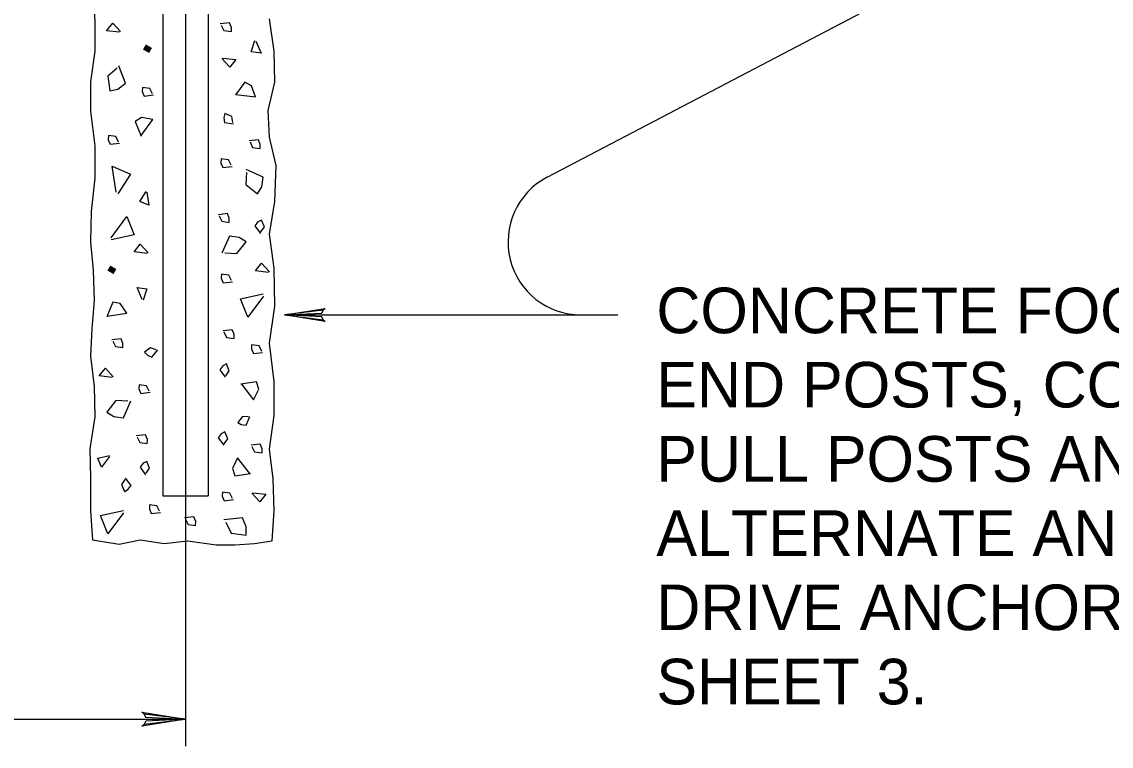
# Model space of a CAD drawing. Extents: x 13 to 918, y -903 to 879.
# Drawn here: x 538 to 612.7, y 510.4 to 560.1 of the extents above; entities that cross this region are included whole.
import ezdxf

# ---------------------------------------------------------------- set-up
doc = ezdxf.new("R2010")
doc.units = 0
doc.layers.add('2', color=7, linetype='Continuous')
doc.layers.add('3', color=7, linetype='Continuous')

msp = doc.modelspace()

# ---------------------------------------------------------------- linework, layer by layer
at = {"layer": '2'}
for p, q in [((549.25425, 631.486), (549.25425, 510.432)), ((547.69175, 615.09225), (547.69175, 527.59225)), ((550.81675, 615.09225), (550.81675, 527.59225)), ((574.03125, 549.41325), (601.00225, 563.55075)), ((556.04375, 539.984), (578.87925, 539.984)), ((581.51675, 538.72775), (581.51675, 538.72775)), ((581.51675, 533.64225), (581.51675, 533.64225)), ((581.51675, 528.557), (581.51675, 528.557)), ((547.69175, 527.59225), (550.81675, 527.59225)), ((542.875, 524.5695), (542.875, 524.5695)), ((549.41875, 524.507), (549.41875, 524.507)), ((555.2, 524.507), (555.2, 524.507)), ((581.51675, 523.4715), (581.51675, 523.4715)), ((581.51675, 518.384), (581.51675, 518.384)), ((399.25425, 512.27975), (549.25425, 512.27975))]:
    msp.add_line(p, q, dxfattribs=at)
for points in [[(542.946, 561.96725), (543.048, 560.02775), (543.048, 558.05075), (542.74175, 555.961), (542.74175, 553.9465), (543.048, 551.56725), (543.048, 549.34225), (542.798, 547.061), (542.74175, 544.9695), (542.9335, 543.05075), (542.98975, 540.961), (542.8375, 539.04225), (542.74175, 537.16325), (542.98975, 535.0715), (543.048, 533.00075), (542.70225, 530.81325), (542.74175, 528.77975), (542.74175, 526.55475), (542.875, 524.5695), (544.71675, 524.2735), (546.15625, 524.57975), (547.7855, 524.32975), (549.41875, 524.507), (551.35425, 524.234), (552.63975, 524.234), (553.98125, 524.32975), (555.2, 524.507), (555.325, 526.55475), (555.26675, 528.74225), (555.01675, 530.77575), (555.325, 533.0965), (555.325, 535.41725), (555.01675, 538.0445), (555.3625, 540.57775), (555.325, 543.186), (555.01675, 545.52575), (555.3625, 547.75075), (555.4585, 550.22575), (555.01675, 552.16325), (554.921, 553.986), (555.3625, 555.9215), (555.325, 558.05075), (555.01675, 560.27575)], [(544.73975, 559.35275), (543.84375, 559.45275), (544.26475, 559.982), (544.80625, 559.39225)], [(551.70225, 559.8465), (551.8855, 559.47575), (552.39375, 559.40275), (552.40225, 559.684), (552.273, 560.00075), (551.6375, 559.92775)], [(554.06675, 558.7445), (554.42925, 557.91725), (553.7605, 558.01725), (554, 558.782)], [(544.5605, 556.89225), (543.9355, 556.3445), (544.06875, 555.32775), (544.61675, 555.457), (545.15, 555.861), (544.68125, 557.05475)], [(551.81475, 557.582), (552.7125, 557.482), (552.29175, 556.95275), (551.748, 557.54225)], [(546.98975, 555.136), (546.80625, 555.507), (546.298, 555.57575), (546.28975, 555.2945), (546.41875, 554.982), (547.05225, 555.05275)], [(552.70425, 555.09225), (554.05, 554.92975), (553.7835, 555.68825), (553.323, 555.92975), (552.675, 555.06325)], [(546.2125, 552.282), (547.025, 553.36725), (546.2355, 553.51525), (545.8, 553.23825), (546.225, 552.24225)], [(552.50625, 553.17575), (552.425, 553.57975), (551.95225, 553.77975), (551.871, 553.509), (551.91475, 553.17575), (552.546, 553.07975)], [(544.6625, 551.82975), (544.47925, 552.20075), (543.971, 552.2695), (543.9625, 551.98825), (544.08975, 551.67775), (544.725, 551.7485)], [(553.673, 551.832), (553.85425, 551.461), (554.36475, 551.38825), (554.373, 551.6695), (554.24375, 551.984), (553.6085, 551.911)], [(544.50425, 548.384), (544.2375, 550.16725), (545.47725, 549.62775), (544.61475, 548.27575)], [(552.38125, 550.234), (552.198, 550.60475), (551.68975, 550.6735), (551.68125, 550.39225), (551.8105, 550.07975), (552.44375, 550.15075)], [(553.43125, 549.74225), (553.37725, 548.91325), (554.18975, 548.28825), (554.4855, 548.76725), (554.57725, 549.42975), (553.40225, 549.94225)], [(546.6125, 548.38825), (546.746, 547.4965), (546.125, 547.76525), (546.55625, 548.44025)], [(544.16475, 545.2735), (545.2355, 546.7235), (545.73125, 545.46525), (544.16475, 545.1195)], [(551.55425, 546.7695), (551.7355, 546.3985), (552.246, 546.32575), (552.25425, 546.607), (552.125, 546.9215), (551.48975, 546.8485)], [(554.423, 545.66525), (554.65425, 546.009), (554.4605, 546.484), (554.2125, 546.35075), (554.00425, 546.084), (554.3835, 545.5695)], [(551.95225, 544.24225), (552.77725, 544.18825), (553.40625, 544.9965), (552.92725, 545.29225), (552.25625, 545.384), (551.74375, 544.21325)], [(546.621, 544.1965), (545.725, 544.2965), (546.146, 544.82575), (546.6875, 544.236)], [(554.94175, 542.8985), (554.046, 542.9985), (554.46675, 543.52775), (555.0085, 542.93825)], [(552.40225, 542.33825), (552.21875, 542.711), (551.7105, 542.77975), (551.70225, 542.4985), (551.82925, 542.186), (552.46475, 542.257)], [(546.29375, 541.036), (545.9335, 541.86325), (546.60225, 541.76325), (546.3605, 540.9985)], [(554.58975, 541.2735), (553.51875, 539.8195), (553.023, 541.07775), (554.5855, 541.42775)], [(543.89375, 539.90075), (545.2355, 540.09225), (544.78125, 540.75475), (544.27725, 540.86725), (543.873, 539.86325)], [(558.69175, 539.65075), (558.59375, 539.84225), (556.04375, 539.984), (558.69175, 539.65075), (558.82925, 539.536), (556.04375, 539.984), (558.59175, 540.109), (558.6855, 540.30075), (556.04375, 539.984), (558.82925, 540.42575), (558.6855, 540.30075)], [(551.88975, 538.81725), (552.071, 538.4465), (552.58125, 538.3735), (552.58975, 538.65475), (552.4605, 538.9695), (551.825, 538.8965)], [(544.26675, 538.19025), (544.448, 537.8195), (544.9585, 537.7465), (544.96675, 538.02775), (544.8375, 538.34225), (544.20225, 538.2695)], [(547.24375, 537.5985), (546.85225, 537.732), (546.44375, 537.4215), (546.6375, 537.21525), (546.946, 537.086), (547.346, 537.586)], [(554.47725, 537.484), (554.29375, 537.85475), (553.7855, 537.9235), (553.77725, 537.64225), (553.90625, 537.32975), (554.53975, 537.40075)], [(544.2355, 535.70275), (543.33975, 535.80275), (543.7605, 536.332), (544.30225, 535.74225)], [(552.021, 535.811), (552.25, 536.15475), (552.05625, 536.62975), (551.8085, 536.4965), (551.60225, 536.22975), (551.98125, 535.71525)], [(553.0835, 535.236), (553.921, 534.1695), (554.26675, 534.8945), (554.1125, 535.39025), (553.04175, 535.236)], [(546.7625, 534.76325), (546.57925, 535.134), (546.071, 535.20275), (546.0625, 534.9215), (546.19175, 534.609), (546.825, 534.67975)], [(545.3085, 534.06725), (544.47925, 534.1215), (543.85425, 533.309), (544.3335, 533.01325), (544.996, 532.9215), (545.5085, 534.0965)], [(553.56475, 533.00275), (553.15225, 533.02975), (552.8375, 532.6235), (553.07725, 532.47575), (553.4125, 532.432), (553.66675, 533.01525)], [(545.94375, 531.61525), (546.125, 531.2445), (546.6355, 531.1715), (546.64375, 531.45275), (546.51475, 531.76725), (545.87925, 531.6945)], [(551.9105, 531.1445), (552.14175, 531.48825), (551.948, 531.96325), (551.7, 531.82975), (551.49175, 531.56325), (551.871, 531.0485)], [(553.80625, 530.9715), (553.9875, 530.60075), (554.498, 530.52775), (554.50625, 530.809), (554.37725, 531.1235), (553.74175, 531.05075)], [(544.0375, 530.2715), (543.50225, 529.5465), (543.25425, 530.17575), (544.0355, 530.3485)], [(553.6605, 529.1215), (552.823, 530.184), (552.47725, 529.46325), (552.63125, 528.96725), (553.70625, 529.1215)], [(546.5585, 529.12975), (546.78975, 529.4735), (546.596, 529.9485), (546.348, 529.81525), (546.13975, 529.5485), (546.51875, 529.034)], [(545.10225, 528.707), (544.873, 528.36325), (545.06475, 527.886), (545.3125, 528.0195), (545.521, 528.28825), (545.13975, 528.80275)], [(552.471, 527.409), (552.2875, 527.77975), (551.77925, 527.8485), (551.771, 527.56725), (551.9, 527.25475), (552.5335, 527.32575)], [(553.86475, 527.80075), (554.7625, 527.70075), (554.34175, 527.1715), (553.798, 527.761)], [(544.998, 526.42775), (543.92725, 524.9735), (543.43125, 526.232), (544.99375, 526.582)], [(547.475, 526.52775), (547.29175, 526.8985), (546.7835, 526.96725), (546.775, 526.686), (546.90425, 526.3735), (547.5375, 526.4445)], [(549.25425, 525.99225), (549.4355, 525.6215), (549.946, 525.5485), (549.95425, 525.82975), (549.825, 526.1445), (549.18975, 526.0715)], [(552.01475, 525.782), (552.38125, 525.04025), (553.398, 524.8985), (553.41475, 525.461), (553.15625, 526.09025), (551.8855, 525.9445)]]:
    msp.add_lwpolyline(points, dxfattribs=at)
msp.add_arc((576.35201, 544.98404), 5, 117.6630361, 270, dxfattribs=at)
at = {"layer": '3'}
msp.add_lwpolyline([(546.41675, 512.636), (546.523, 512.42975), (549.25425, 512.27975), (546.41675, 512.636), (546.271, 512.761), (549.25425, 512.27975), (546.525, 512.1445), (546.425, 511.94225), (549.25425, 512.27975), (546.271, 511.80475), (546.425, 511.94225)], dxfattribs=at)

# ---------------------------------------------------------------- texts
at = {"layer": '2'}
for p in [(546.56675, 557.5985), (544.12925, 542.45075)]:
    msp.add_text('.', height=3.125, rotation=60, dxfattribs=at).set_placement(p)
at = {"layer": '3'}
for s, height, p in [('CONCRETE FOOTING FOR', 3.1249995, (581.51675, 538.72775)), ('END POSTS, CORNER POSTS,', 3.1249995, (581.51675, 533.64225)), ('PULL POSTS AND BRACES.  FOR', 3.1249995, (581.51675, 528.557)), ('ALTERNATE ANCHORING, SEE', 3.1249995, (581.51675, 523.4715)), ('DRIVE ANCHORING DETAILS, RC-60M,', 3.1249995, (581.51675, 518.384)), ('SHEET 3.', 3.124999, (581.51675, 513.2985))]:
    msp.add_text(s, height=height, dxfattribs=at).set_placement(p)

doc.saveas('drawing.dxf')
